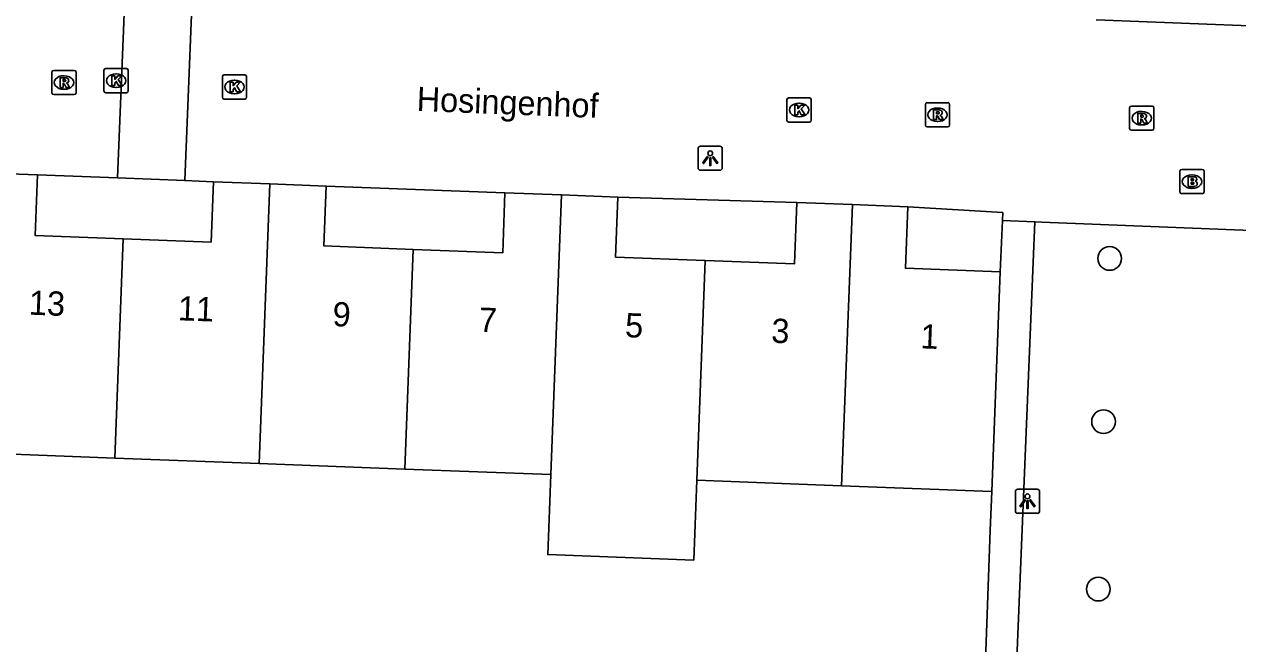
# Model space of a CAD drawing. Extents: x 160787 to 161428, y 386828 to 387483.
# Drawn here: x 161233.8 to 161283.9, y 387188.4 to 387214 of the extents above; entities that cross this region are included whole.
import ezdxf

# ---------------------------------------------------------------- set-up
doc = ezdxf.new("R2010")
doc.units = 0
for name, color, linetype in [('IMGEO_Boom', 7, 'Continuous'), ('IMGEO_Brandkraan', 7, 'Continuous'), ('IMGEO_Kolk', 7, 'Continuous'), ('IMGEO_Lichtpunt', 7, 'Continuous'), ('IMGEO_Muur', 7, 'Continuous'), ('IMGEO_Openbare_ruimte_label', 7, 'Continuous'), ('IMGEO_Pand', 7, 'Continuous'), ('IMGEO_Pand_nummerreeks', 7, 'Continuous'), ('IMGEO_Rijbaan_lokaal_open', 7, 'Continuous'), ('IMGEO_Rioolput', 7, 'Continuous'), ('IMGEO_Voetpad_open', 7, 'Continuous')]:
    doc.layers.add(name, color=color, linetype=linetype)

msp = doc.modelspace()

# ---------------------------------------------------------------- linework, layer by layer
at = {"layer": 'IMGEO_Boom'}
for centre in [(161278.63, 387204.353), (161278.378, 387197.612), (161278.164, 387190.694)]:
    msp.add_circle(centre, 0.489, dxfattribs=at)
at = {"layer": 'IMGEO_Brandkraan'}
for p, q in [((161281.531, 387207.102), (161281.531, 387207.954)), ((161281.606, 387208.028), (161282.458, 387208.028)), ((161282.019, 387207.808), (161282.044, 387207.808)), ((161282.532, 387207.954), (161282.532, 387207.102)), ((161282.042, 387207.248), (161282.017, 387207.248)), ((161282.458, 387207.028), (161281.606, 387207.028))]:
    msp.add_line(p, q, dxfattribs=at)
for points in [[(161281.531, 387207.102), (161281.531, 387207.954)], [(161281.606, 387208.028), (161282.458, 387208.028)], [(161281.879, 387207.728), (161281.879, 387207.328), (161282.092, 387207.328)], [(161282.11, 387207.728), (161281.879, 387207.728)], [(161282.532, 387207.954), (161282.532, 387207.102)], [(161282.058, 387207.647), (161282.004, 387207.647), (161282.004, 387207.571)], [(161282.004, 387207.571), (161282.057, 387207.571)], [(161282.066, 387207.495), (161282.004, 387207.495), (161282.004, 387207.414)], [(161282.004, 387207.414), (161282.066, 387207.414)], [(161282.458, 387207.028), (161281.606, 387207.028)]]:
    msp.add_lwpolyline(points, dxfattribs=at)
for centre, radius, start, end in [((161281.608, 387207.952), 0.0765, 91.552, 178.448), ((161281.608, 387207.952), 0.0765, 91.552, 178.448), ((161282.114, 387207.583), 0.145, 59.4692, 91.5367), ((161282.139, 387207.63), 0.0922, 285.5137, 58.1501), ((161282.456, 387207.952), 0.0765, 1.552, 88.448), ((161282.456, 387207.952), 0.0765, 1.552, 88.448), ((161282.059, 387207.609), 0.0379, 267.8285, 90.9355), ((161282.067, 387207.454), 0.0404, 269.8759, 90.5077), ((161282.098, 387207.579), 0.251, 268.6676, 293.5347), ((161282.144, 387207.438), 0.105, 301.3115, 78.989), ((161281.608, 387207.104), 0.0765, 181.552, 268.448), ((161281.608, 387207.104), 0.0765, 181.552, 268.448), ((161282.456, 387207.104), 0.0765, 271.552, 358.448), ((161282.456, 387207.104), 0.0765, 271.552, 358.448)]:
    msp.add_arc(centre, radius, start, end, dxfattribs=at)
for centre, major_axis, ratio, start_param, end_param in [((161282.018, 387207.528), (-0.387, 0.002), 0.722429, 4.712389, 7.853982), ((161282.043, 387207.528), (-0.39, 0.002), 0.717154, 1.570796, 4.712389)]:
    msp.add_ellipse(centre, major_axis=major_axis, ratio=ratio, start_param=start_param, end_param=end_param, dxfattribs=at)
at = {"layer": 'IMGEO_Kolk'}
for p, q in [((161237.172, 387212.198), (161238.024, 387212.198)), ((161237.097, 387211.272), (161237.097, 387212.124)), ((161237.585, 387211.978), (161237.61, 387211.978)), ((161238.098, 387212.124), (161238.098, 387211.272)), ((161241.985, 387211.009), (161241.985, 387211.861)), ((161242.06, 387211.935), (161242.912, 387211.935)), ((161242.473, 387211.715), (161242.498, 387211.715)), ((161242.986, 387211.861), (161242.986, 387211.009)), ((161238.024, 387211.198), (161237.172, 387211.198)), ((161237.608, 387211.418), (161237.583, 387211.418)), ((161242.912, 387210.935), (161242.06, 387210.935)), ((161242.496, 387211.155), (161242.471, 387211.155)), ((161265.304, 387210.06), (161265.304, 387210.912)), ((161265.379, 387210.986), (161266.231, 387210.986)), ((161265.792, 387210.766), (161265.817, 387210.766)), ((161266.305, 387210.912), (161266.305, 387210.06)), ((161265.815, 387210.206), (161265.79, 387210.206)), ((161266.231, 387209.986), (161265.379, 387209.986))]:
    msp.add_line(p, q, dxfattribs=at)
for points in [[(161237.172, 387212.198), (161238.024, 387212.198)], [(161237.097, 387211.272), (161237.097, 387212.124)], [(161237.418, 387211.898), (161237.541, 387211.898), (161237.541, 387211.747), (161237.671, 387211.898), (161237.835, 387211.898), (161237.689, 387211.747), (161237.842, 387211.498), (161237.69, 387211.498), (161237.605, 387211.662), (161237.541, 387211.595), (161237.541, 387211.498), (161237.418, 387211.498), (161237.418, 387211.898)], [(161238.098, 387212.124), (161238.098, 387211.272)], [(161241.985, 387211.009), (161241.985, 387211.861)], [(161242.06, 387211.935), (161242.912, 387211.935)], [(161242.986, 387211.861), (161242.986, 387211.009)], [(161238.024, 387211.198), (161237.172, 387211.198)], [(161242.306, 387211.635), (161242.429, 387211.635), (161242.429, 387211.484), (161242.559, 387211.635), (161242.723, 387211.635), (161242.577, 387211.484), (161242.73, 387211.235), (161242.578, 387211.235), (161242.493, 387211.399), (161242.429, 387211.332), (161242.429, 387211.235), (161242.306, 387211.235), (161242.306, 387211.635)], [(161242.912, 387210.935), (161242.06, 387210.935)], [(161265.304, 387210.06), (161265.304, 387210.912)], [(161265.379, 387210.986), (161266.231, 387210.986)], [(161265.625, 387210.686), (161265.748, 387210.686), (161265.748, 387210.535), (161265.878, 387210.686), (161266.042, 387210.686), (161265.896, 387210.535), (161266.049, 387210.286), (161265.897, 387210.286), (161265.812, 387210.45), (161265.748, 387210.383), (161265.748, 387210.286), (161265.625, 387210.286), (161265.625, 387210.686)], [(161266.305, 387210.912), (161266.305, 387210.06)], [(161266.231, 387209.986), (161265.379, 387209.986)]]:
    msp.add_lwpolyline(points, dxfattribs=at)
for centre, start, end in [((161237.174, 387212.122), 91.552, 178.448), ((161237.174, 387212.122), 91.552, 178.448), ((161238.022, 387212.122), 1.552, 88.448), ((161238.022, 387212.122), 1.552, 88.448), ((161242.062, 387211.859), 91.552, 178.448), ((161242.062, 387211.859), 91.552, 178.448), ((161242.91, 387211.859), 1.552, 88.448), ((161242.91, 387211.859), 1.552, 88.448), ((161237.174, 387211.274), 181.552, 268.448), ((161237.174, 387211.274), 181.552, 268.448), ((161238.022, 387211.274), 271.552, 358.448), ((161238.022, 387211.274), 271.552, 358.448), ((161242.062, 387211.011), 181.552, 268.448), ((161242.062, 387211.011), 181.552, 268.448), ((161242.91, 387211.011), 271.552, 358.448), ((161242.91, 387211.011), 271.552, 358.448), ((161265.381, 387210.91), 91.552, 178.448), ((161265.381, 387210.91), 91.552, 178.448), ((161266.229, 387210.91), 1.552, 88.448), ((161266.229, 387210.91), 1.552, 88.448), ((161265.381, 387210.062), 181.552, 268.448), ((161265.381, 387210.062), 181.552, 268.448), ((161266.229, 387210.062), 271.552, 358.448), ((161266.229, 387210.062), 271.552, 358.448)]:
    msp.add_arc(centre, 0.0765, start, end, dxfattribs=at)
for centre, major_axis, ratio, start_param, end_param in [((161237.584, 387211.698), (-0.387, 0.002), 0.722429, 4.712389, 7.853982), ((161237.609, 387211.698), (-0.39, 0.002), 0.717154, 1.570796, 4.712389), ((161242.472, 387211.435), (-0.387, 0.002), 0.722429, 4.712389, 7.853982), ((161242.497, 387211.435), (-0.39, 0.002), 0.717154, 1.570796, 4.712389), ((161265.791, 387210.486), (-0.387, 0.002), 0.722429, 4.712389, 7.853982), ((161265.816, 387210.486), (-0.39, 0.002), 0.717154, 1.570796, 4.712389)]:
    msp.add_ellipse(centre, major_axis=major_axis, ratio=ratio, start_param=start_param, end_param=end_param, dxfattribs=at)
at = {"layer": 'IMGEO_Lichtpunt'}
for p, q in [((161261.636, 387208.895), (161261.636, 387208.088)), ((161261.636, 387208.895), (161261.636, 387208.088)), ((161262.538, 387208.99), (161261.73, 387208.99)), ((161262.538, 387208.99), (161261.73, 387208.99)), ((161262.632, 387208.088), (161262.632, 387208.895)), ((161262.632, 387208.088), (161262.632, 387208.895)), ((161261.73, 387207.994), (161262.538, 387207.994)), ((161261.73, 387207.994), (161262.538, 387207.994)), ((161274.74, 387194.726), (161274.74, 387193.919)), ((161274.74, 387194.726), (161274.74, 387193.919)), ((161275.642, 387194.821), (161274.834, 387194.821)), ((161275.642, 387194.821), (161274.834, 387194.821)), ((161275.736, 387193.919), (161275.736, 387194.726)), ((161275.736, 387193.919), (161275.736, 387194.726)), ((161274.834, 387193.825), (161275.642, 387193.825)), ((161274.834, 387193.825), (161275.642, 387193.825))]:
    msp.add_line(p, q, dxfattribs=at)
for points in [[(161262.01, 387208.559), (161262.049, 387208.531), (161261.861, 387208.269), (161261.823, 387208.296), (161262.01, 387208.559)], [(161262.112, 387208.511), (161262.159, 387208.511), (161262.159, 387208.189), (161262.112, 387208.189), (161262.112, 387208.511)], [(161262.222, 387208.531), (161262.26, 387208.558), (161262.447, 387208.296), (161262.408, 387208.268), (161262.222, 387208.531)], [(161275.114, 387194.39), (161275.153, 387194.362), (161274.965, 387194.1), (161274.927, 387194.127), (161275.114, 387194.39)], [(161275.216, 387194.342), (161275.263, 387194.342), (161275.263, 387194.02), (161275.216, 387194.02), (161275.216, 387194.342)], [(161275.326, 387194.362), (161275.364, 387194.389), (161275.551, 387194.127), (161275.512, 387194.099), (161275.326, 387194.362)]]:
    msp.add_lwpolyline(points, dxfattribs=at)
for centre in [(161262.135, 387208.693), (161275.239, 387194.524)]:
    msp.add_circle(centre, 0.0994, dxfattribs=at)
for centre, start, end in [((161261.73, 387208.895), 90, 180), ((161261.73, 387208.895), 90, 180), ((161262.538, 387208.895), 0, 90), ((161262.538, 387208.895), 0, 90), ((161261.73, 387208.088), 180, 270), ((161261.73, 387208.088), 180, 270), ((161262.538, 387208.088), 270, 0), ((161262.538, 387208.088), 270, 360), ((161274.834, 387194.726), 90, 180), ((161274.834, 387194.726), 90, 180), ((161275.642, 387194.726), 0, 90), ((161275.642, 387194.726), 0, 90), ((161274.834, 387193.919), 180, 270), ((161274.834, 387193.919), 180, 270), ((161275.642, 387193.919), 270, 0), ((161275.642, 387193.919), 270, 360)]:
    msp.add_arc(centre, 0.0946, start, end, dxfattribs=at)
at = {"layer": 'IMGEO_Muur'}
msp.add_lwpolyline([(161273.76, 387194.728), (161273.702, 387193.11)], dxfattribs=at)
at = {"layer": 'IMGEO_Pand'}
for points in [[(161232.03, 387207.895), (161234.345, 387207.807)], [(161237.885, 387205.165), (161234.25, 387205.304), (161234.345, 387207.807)], [(161241.615, 387207.521), (161241.52, 387205.027), (161237.885, 387205.165)], [(161241.615, 387207.521), (161243.942, 387207.432)], [(161243.942, 387207.432), (161243.502, 387195.881)], [(161243.942, 387207.432), (161246.271, 387207.343)], [(161249.87, 387204.728), (161246.177, 387204.869), (161246.271, 387207.343)], [(161253.658, 387207.063), (161253.563, 387204.587), (161249.87, 387204.728)], [(161253.658, 387207.063), (161255.99, 387206.975)], [(161255.99, 387206.975), (161255.55, 387195.422)], [(161255.99, 387206.975), (161258.322, 387206.886)], [(161261.925, 387204.27), (161258.228, 387204.411), (161258.322, 387206.886)], [(161265.715, 387206.665), (161265.618, 387204.13), (161261.925, 387204.27)], [(161265.715, 387206.665), (161268.005, 387206.578)], [(161267.563, 387194.964), (161268.005, 387206.578)], [(161268.005, 387206.578), (161270.296, 387206.49)], [(161270.296, 387206.49), (161270.199, 387203.947), (161274.106, 387203.798)], [(161237.54, 387196.109), (161237.885, 387205.165)], [(161249.524, 387195.652), (161249.87, 387204.728)], [(161261.925, 387204.27), (161261.579, 387195.192)], [(161274.106, 387203.798), (161273.76, 387194.728)], [(161237.54, 387196.109), (161231.59, 387196.335)], [(161243.502, 387195.881), (161237.54, 387196.109)], [(161249.524, 387195.652), (161243.502, 387195.881)], [(161255.55, 387195.422), (161249.524, 387195.652)], [(161261.579, 387195.192), (161261.452, 387191.894), (161255.425, 387192.124), (161255.55, 387195.422)], [(161267.563, 387194.964), (161261.579, 387195.192)], [(161273.76, 387194.728), (161267.563, 387194.964)]]:
    msp.add_lwpolyline(points, dxfattribs=at)
at = {"layer": 'IMGEO_Rijbaan_lokaal_open'}
for points in [[(161237.659, 387207.677), (161237.967, 387215.47)], [(161240.747, 387215.462), (161240.436, 387207.567)], [(161299.195, 387213.381), (161278.076, 387214.209)], [(161234.345, 387207.807), (161237.659, 387207.677)], [(161237.659, 387207.677), (161240.436, 387207.567)], [(161240.436, 387207.567), (161241.615, 387207.521)], [(161246.271, 387207.343), (161253.658, 387207.063)], [(161258.322, 387206.886), (161265.715, 387206.665)], [(161274.202, 387205.923), (161274.217, 387206.248), (161270.296, 387206.49)], [(161274.202, 387205.923), (161275.544, 387205.862)], [(161291.402, 387205.236), (161275.836, 387205.849), (161275.544, 387205.862)]]:
    msp.add_lwpolyline(points, dxfattribs=at)
at = {"layer": 'IMGEO_Rioolput'}
for p, q in [((161234.944, 387211.192), (161234.944, 387212.044)), ((161235.019, 387212.118), (161235.871, 387212.118)), ((161235.432, 387211.898), (161235.457, 387211.898)), ((161235.945, 387212.044), (161235.945, 387211.192)), ((161235.455, 387211.338), (161235.43, 387211.338)), ((161235.871, 387211.118), (161235.019, 387211.118)), ((161271.02, 387209.86), (161271.02, 387210.712)), ((161271.095, 387210.786), (161271.947, 387210.786)), ((161272.021, 387210.712), (161272.021, 387209.86)), ((161271.508, 387210.566), (161271.533, 387210.566)), ((161279.455, 387209.719), (161279.455, 387210.571)), ((161279.53, 387210.645), (161280.382, 387210.645)), ((161279.943, 387210.425), (161279.968, 387210.425)), ((161280.456, 387210.571), (161280.456, 387209.719)), ((161271.947, 387209.786), (161271.095, 387209.786)), ((161271.531, 387210.006), (161271.506, 387210.006)), ((161279.966, 387209.865), (161279.941, 387209.865)), ((161280.382, 387209.645), (161279.53, 387209.645))]:
    msp.add_line(p, q, dxfattribs=at)
for points in [[(161234.944, 387211.192), (161234.944, 387212.044)], [(161235.019, 387212.118), (161235.871, 387212.118)], [(161235.533, 387211.816), (161235.281, 387211.818), (161235.281, 387211.418)], [(161235.459, 387211.737), (161235.405, 387211.737), (161235.405, 387211.656)], [(161235.945, 387212.044), (161235.945, 387211.192)], [(161235.281, 387211.418), (161235.405, 387211.418), (161235.405, 387211.58), (161235.416, 387211.58)], [(161235.405, 387211.656), (161235.457, 387211.656)], [(161235.463, 387211.551), (161235.534, 387211.418), (161235.674, 387211.418), (161235.609, 387211.544)], [(161235.871, 387211.118), (161235.019, 387211.118)], [(161271.02, 387209.86), (161271.02, 387210.712)], [(161271.095, 387210.786), (161271.947, 387210.786)], [(161272.021, 387210.712), (161272.021, 387209.86)], [(161271.609, 387210.484), (161271.357, 387210.486), (161271.357, 387210.086)], [(161271.357, 387210.086), (161271.481, 387210.086), (161271.481, 387210.248), (161271.492, 387210.248)], [(161271.535, 387210.405), (161271.481, 387210.405), (161271.481, 387210.324)], [(161271.481, 387210.324), (161271.533, 387210.324)], [(161271.539, 387210.219), (161271.61, 387210.086), (161271.75, 387210.086), (161271.685, 387210.212)], [(161279.455, 387209.719), (161279.455, 387210.571)], [(161279.53, 387210.645), (161280.382, 387210.645)], [(161280.044, 387210.343), (161279.792, 387210.345), (161279.792, 387209.945)], [(161279.97, 387210.264), (161279.916, 387210.264), (161279.916, 387210.183)], [(161279.916, 387210.183), (161279.968, 387210.183)], [(161280.456, 387210.571), (161280.456, 387209.719)], [(161271.947, 387209.786), (161271.095, 387209.786)], [(161279.792, 387209.945), (161279.916, 387209.945), (161279.916, 387210.107), (161279.927, 387210.107)], [(161279.974, 387210.078), (161280.045, 387209.945), (161280.185, 387209.945), (161280.12, 387210.071)], [(161280.382, 387209.645), (161279.53, 387209.645)]]:
    msp.add_lwpolyline(points, dxfattribs=at)
for centre, radius, start, end in [((161235.021, 387212.042), 0.0765, 91.552, 178.448), ((161235.021, 387212.042), 0.0765, 91.552, 178.448), ((161235.465, 387211.641), 0.0964, 77.0061, 93.1865), ((161235.479, 387211.698), 0.0378, 276.6634, 79.6772), ((161235.532, 387211.706), 0.109, 350.3612, 89.416), ((161235.53, 387211.706), 0.112, 277.5842, 350.9817), ((161235.869, 387212.042), 0.0765, 1.552, 88.448), ((161235.869, 387212.042), 0.0765, 1.552, 88.448), ((161235.021, 387211.194), 0.0765, 181.552, 268.448), ((161235.021, 387211.194), 0.0765, 181.552, 268.448), ((161235.415, 387211.527), 0.0533, 26.0293, 88.6989), ((161235.441, 387211.845), 0.19, 274.7715, 282.9687), ((161235.514, 387211.491), 0.108, 29.5134, 73.7905), ((161235.869, 387211.194), 0.0765, 271.552, 358.448), ((161235.869, 387211.194), 0.0765, 271.552, 358.448), ((161271.097, 387210.71), 0.0765, 91.552, 178.448), ((161271.097, 387210.71), 0.0765, 91.552, 178.448), ((161271.945, 387210.71), 0.0765, 1.552, 88.448), ((161271.945, 387210.71), 0.0765, 1.552, 88.448), ((161271.491, 387210.195), 0.0533, 26.0293, 88.6989), ((161271.517, 387210.513), 0.19, 274.7715, 282.9687), ((161271.541, 387210.309), 0.0964, 77.0061, 93.1865), ((161271.555, 387210.366), 0.0378, 276.6634, 79.6772), ((161271.608, 387210.374), 0.109, 350.3612, 89.416), ((161271.606, 387210.374), 0.112, 277.5842, 350.9817), ((161271.59, 387210.159), 0.108, 29.5134, 73.7905), ((161279.532, 387210.569), 0.0765, 91.552, 178.448), ((161279.532, 387210.569), 0.0765, 91.552, 178.448), ((161279.952, 387210.372), 0.19, 274.7715, 282.9687), ((161279.976, 387210.168), 0.0964, 77.0061, 93.1865), ((161279.99, 387210.225), 0.0378, 276.6634, 79.6772), ((161280.043, 387210.233), 0.109, 350.3612, 89.416), ((161280.041, 387210.233), 0.112, 277.5842, 350.9817), ((161280.38, 387210.569), 0.0765, 1.552, 88.448), ((161280.38, 387210.569), 0.0765, 1.552, 88.448), ((161271.097, 387209.862), 0.0765, 181.552, 268.448), ((161271.097, 387209.862), 0.0765, 181.552, 268.448), ((161271.945, 387209.862), 0.0765, 271.552, 358.448), ((161271.945, 387209.862), 0.0765, 271.552, 358.448), ((161279.532, 387209.721), 0.0765, 181.552, 268.448), ((161279.532, 387209.721), 0.0765, 181.552, 268.448), ((161279.926, 387210.054), 0.0533, 26.0293, 88.6989), ((161280.025, 387210.018), 0.108, 29.5134, 73.7905), ((161280.38, 387209.721), 0.0765, 271.552, 358.448), ((161280.38, 387209.721), 0.0765, 271.552, 358.448)]:
    msp.add_arc(centre, radius, start, end, dxfattribs=at)
for centre, major_axis, ratio, start_param, end_param in [((161235.431, 387211.618), (-0.387, 0.002), 0.722429, 4.712389, 7.853982), ((161235.456, 387211.618), (-0.39, 0.002), 0.717154, 1.570796, 4.712389), ((161271.507, 387210.286), (-0.387, 0.002), 0.722429, 4.712389, 7.853982), ((161271.532, 387210.286), (-0.39, 0.002), 0.717154, 1.570796, 4.712389), ((161279.942, 387210.145), (-0.387, 0.002), 0.722429, 4.712389, 7.853982), ((161279.967, 387210.145), (-0.39, 0.002), 0.717154, 1.570796, 4.712389)]:
    msp.add_ellipse(centre, major_axis=major_axis, ratio=ratio, start_param=start_param, end_param=end_param, dxfattribs=at)
at = {"layer": 'IMGEO_Voetpad_open'}
for points in [[(161274.106, 387203.798), (161274.202, 387205.923)], [(161275.544, 387205.862), (161274.672, 387184.815), (161274.672, 387184.136), (161274.676, 387183.739), (161274.704, 387183.178)], [(161200.679, 387184.363), (161273.288, 387181.587), (161273.702, 387193.11), (161273.76, 387194.728)]]:
    msp.add_lwpolyline(points, dxfattribs=at)

# ---------------------------------------------------------------- texts
at = {"layer": 'IMGEO_Openbare_ruimte_label'}
msp.add_text('Hosingenhof', height=1, rotation=357.7644, dxfattribs=at).set_placement((161249.999, 387210.447))
at = {"layer": 'IMGEO_Pand_nummerreeks'}
for s, p in [('13', (161233.984, 387202.032)), ('11', (161240.139, 387201.8)), ('9', (161246.524, 387201.559)), ('7', (161252.565, 387201.33)), ('5', (161258.605, 387201.102)), ('3', (161264.646, 387200.874)), ('1', (161270.8, 387200.641))]:
    msp.add_text(s, height=1, rotation=357.835, dxfattribs=at).set_placement(p)

doc.saveas('drawing.dxf')
